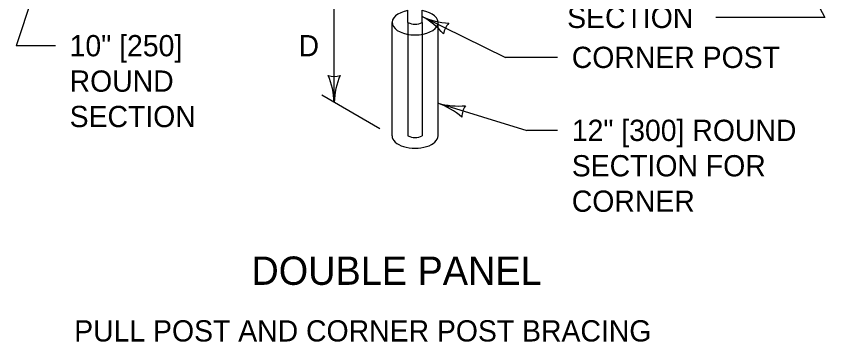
# Model space of a CAD drawing. Extents: x 49973.1 to 50021, y 49987.6 to 50015.4.
# Drawn here: x 50000.731 to 50003.017, y 49993.703 to 49994.622 of the extents above; entities that cross this region are included whole.
import ezdxf

# ---------------------------------------------------------------- set-up
doc = ezdxf.new("R2010")
doc.units = 0
for name, color, linetype in [('Level 1', 7, 'Continuous'), ('Level 2', 7, 'Continuous'), ('Level 3', 7, 'Continuous'), ('Level 4', 7, 'Continuous')]:
    doc.layers.add(name, color=color, linetype=linetype)

msp = doc.modelspace()

# ---------------------------------------------------------------- linework, layer by layer
at = {"layer": 'Level 1'}
for p, q in [((50001.8391, 49994.6044), (50001.8391, 49994.639)), ((50001.8791, 49994.6044), (50001.8791, 49994.6392)), ((50001.7941, 49994.2844), (50001.7941, 49994.6044)), ((50001.9241, 49994.2844), (50001.9241, 49994.6044))]:
    msp.add_line(p, q, dxfattribs=at)
msp.add_arc((50001.8591, 49994.6403), 0.041, 240.8333, 299.1667, dxfattribs=at)
for centre, major_axis, ratio, start_param, end_param in [((50001.8591, 49994.6044), (0.065, 0), 0.543263, 1.883563, 7.541224), ((50001.8591, 49994.2844), (-0.065, 0), 0.54167, 0, 3.141593)]:
    msp.add_ellipse(centre, major_axis=major_axis, ratio=ratio, start_param=start_param, end_param=end_param, dxfattribs=at)
at = {"layer": 'Level 3'}
for p, q in [((50000.8439, 49994.8764), (50000.7315, 49994.5389)), ((50002.8792, 49994.8766), (50003.0175, 49994.6188)), ((50001.6305, 49994.3789), (50001.6305, 49994.699)), ((50001.8791, 49994.6215), (50002.1147, 49994.5059)), ((50003.0175, 49994.6188), (50002.7096, 49994.6188)), ((50000.8426, 49994.5389), (50000.7315, 49994.5389)), ((50002.2622, 49994.5059), (50002.1147, 49994.5059)), ((50001.7595, 49994.3044), (50001.5959, 49994.3989)), ((50001.9241, 49994.3763), (50002.1751, 49994.2998)), ((50002.2622, 49994.2998), (50002.1751, 49994.2998))]:
    msp.add_line(p, q, dxfattribs=at)
for centre, radius, start, end in [((50001.7705, 49994.4275), 0.2223, 40.5672, 60.7507), ((50001.9741, 49994.8342), 0.233, 245.9385, 265.1884), ((50001.9935, 49994.5635), 0.0548, 135.25, 170.9724), ((50001.6305, 49994.5071), 0.0548, 252.1388, 287.8612), ((50001.3978, 49994.3674), 0.233, 2.8273, 22.0772), ((50001.8526, 49994.3697), 0.2223, 157.456, 177.6395), ((50001.8478, 49994.1675), 0.2223, 49.7405, 69.924), ((50001.984, 49994.6015), 0.233, 255.1118, 274.3617), ((50002.0462, 49994.3373), 0.0548, 144.4233, 180.1457)]:
    msp.add_arc(centre, radius, start, end, dxfattribs=at)
at = {"layer": 'Level 4'}
for p, q in [((50001.8391, 49994.6044), (50001.8391, 49994.2844)), ((50001.8791, 49994.6044), (50001.8791, 49994.2844))]:
    msp.add_line(p, q, dxfattribs=at)
msp.add_arc((50001.8591, 49994.3203), 0.041, 240.8333, 299.1667, dxfattribs=at)

# ---------------------------------------------------------------- texts
at = {"layer": 'Level 2'}
for s, height, p in [('SECTION', 0.06, (50002.2891, 49994.5888)), ('10" [250]', 0.06, (50000.8826, 49994.5089)), ('D', 0.06, (50001.5298, 49994.5089)), ('CORNER POST', 0.06, (50002.3022, 49994.4759)), ('ROUND', 0.06, (50000.8826, 49994.4089)), ('SECTION', 0.06, (50000.8826, 49994.3089)), ('12" [300] ROUND', 0.06, (50002.3022, 49994.2698)), ('SECTION FOR', 0.06, (50002.3022, 49994.1698)), ('CORNER', 0.06, (50002.3022, 49994.0698)), ('DOUBLE PANEL', 0.08, (50001.3965, 49993.8635)), ('PULL POST AND CORNER POST BRACING', 0.06, (50000.8955, 49993.7035))]:
    msp.add_text(s, height=height, dxfattribs=at).set_placement(p)

doc.saveas('drawing.dxf')
